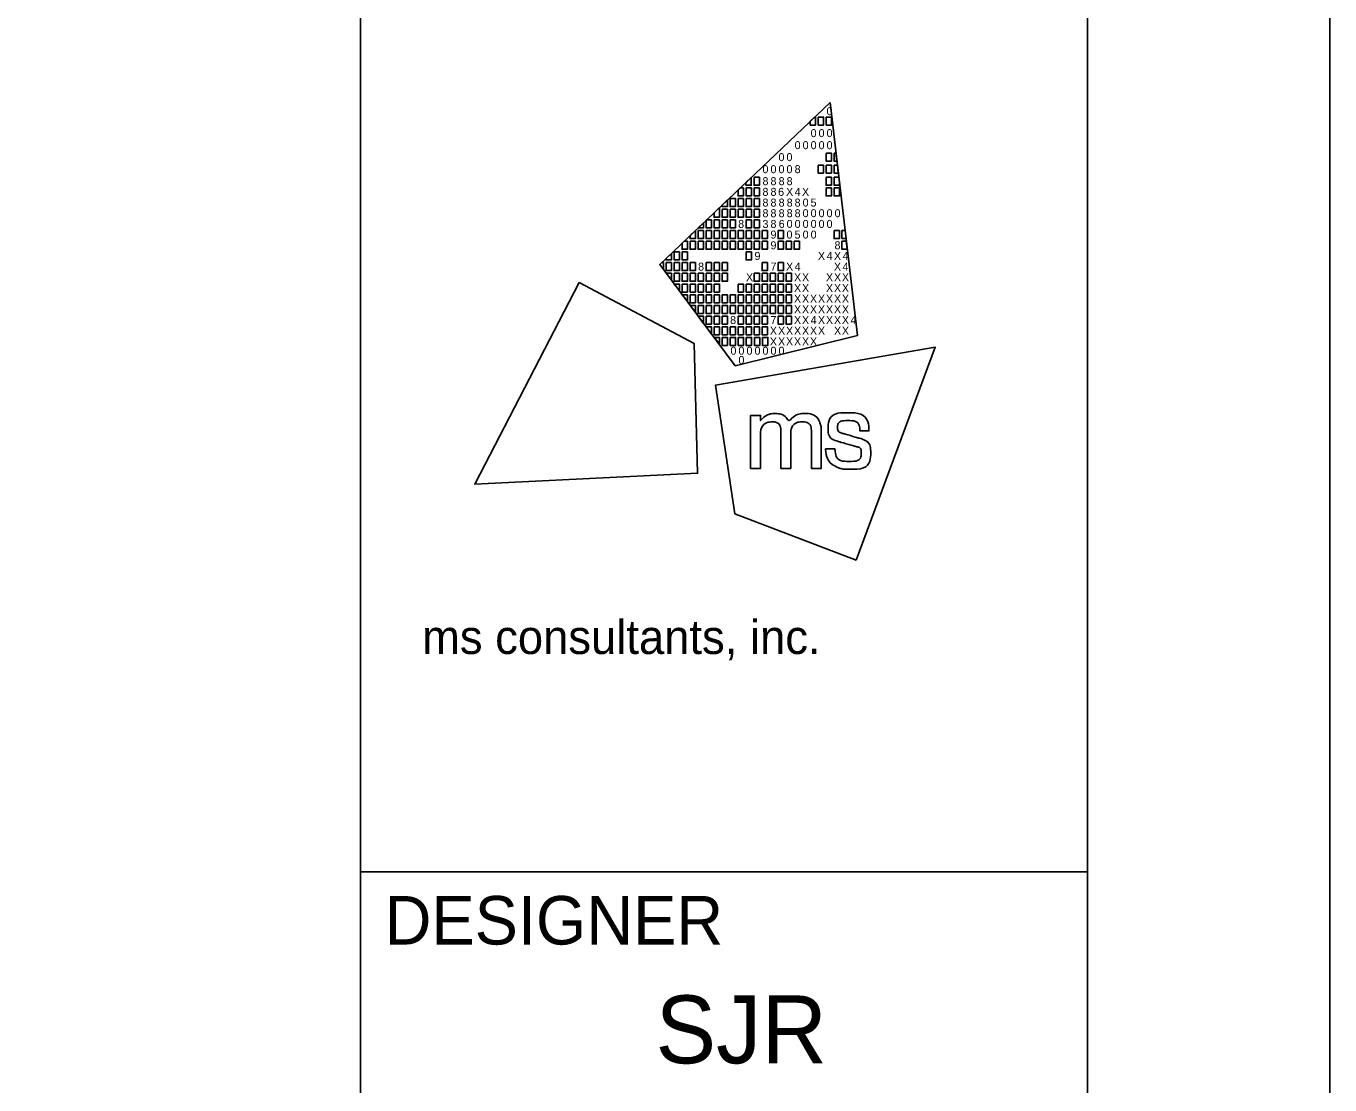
# Model space of a CAD drawing. Extents: x 0 to 34, y 0 to 22.
# Drawn here: x 31.31 to 34, y 2.061 to 4.243 of the extents above; entities that cross this region are included whole.
import ezdxf

# ---------------------------------------------------------------- set-up
doc = ezdxf.new("R2010")
doc.units = 0
for name, color, linetype in [('SH_Border', 7, 'Continuous'), ('SH_Cut_Line', 7, 'Continuous'), ('SH_Data', 7, 'Continuous'), ('SH_Text', 7, 'Continuous')]:
    doc.layers.add(name, color=color, linetype=linetype)

msp = doc.modelspace()

# ---------------------------------------------------------------- linework, layer by layer
at = {"layer": 'SH_Border'}
for p, q in [((32, 0.5), (32, 21.5)), ((32, 2.5), (33.5, 2.5))]:
    msp.add_line(p, q, dxfattribs=at)
msp.add_lwpolyline([(1.5, 21.5), (33.5, 21.5), (33.5, 0.5), (1.5, 0.5)], close=True, dxfattribs=at)
at = {"layer": 'SH_Cut_Line'}
msp.add_lwpolyline([(0, 0), (34, 0), (34, 22), (0, 22)], close=True, dxfattribs=at)
at = {"layer": 'SH_Data'}
msp.add_line((32.75, 3.5), (32.75, 3.5), dxfattribs=at)
at = {"layer": 'SH_Text'}
for p, q in [((32.6175, 3.7519), (32.9688, 4.0861)), ((32.9688, 4.0861), (32.9688, 4.0861)), ((32.9688, 4.0861), (33.0253, 3.6052)), ((32.773, 3.543), (32.6175, 3.7519)), ((33.0253, 3.6052), (32.773, 3.543))]:
    msp.add_line(p, q, dxfattribs=at)
for points in [[(32.9279, 4.0472), (32.9369, 4.0558), (32.9389, 4.0558), (32.9389, 4.0393), (32.9279, 4.0393)], [(32.9444, 4.0558), (32.9554, 4.0558), (32.9554, 4.0393), (32.9444, 4.0393)], [(32.9609, 4.0558), (32.9719, 4.0558), (32.9719, 4.0393), (32.9609, 4.0393)], [(32.9606, 3.9815), (32.9716, 3.9815), (32.9716, 3.965), (32.9606, 3.965)], [(32.9771, 3.9815), (32.9811, 3.9815), (32.983, 3.965), (32.9771, 3.965)], [(32.9441, 3.9567), (32.9551, 3.9567), (32.9551, 3.9402), (32.9441, 3.9402)], [(32.9606, 3.9567), (32.9716, 3.9567), (32.9716, 3.9402), (32.9606, 3.9402)], [(32.9771, 3.9567), (32.984, 3.9567), (32.9859, 3.9402), (32.9771, 3.9402)], [(32.7953, 3.9211), (32.8064, 3.9316), (32.8064, 3.9154), (32.7953, 3.9154)], [(32.8123, 3.9319), (32.8233, 3.9319), (32.8233, 3.9154), (32.8123, 3.9154)], [(32.9606, 3.9319), (32.9716, 3.9319), (32.9716, 3.9154), (32.9606, 3.9154)], [(32.9771, 3.9319), (32.9869, 3.9319), (32.9881, 3.9218), (32.9881, 3.9154), (32.9771, 3.9154)], [(32.7958, 3.9099), (32.8068, 3.9099), (32.8068, 3.8934), (32.7958, 3.8934)], [(32.8123, 3.9099), (32.8233, 3.9099), (32.8233, 3.8934), (32.8123, 3.8934)], [(32.9606, 3.9099), (32.9716, 3.9099), (32.9716, 3.8934), (32.9606, 3.8934)], [(32.9771, 3.9099), (32.9881, 3.9099), (32.9881, 3.8934), (32.9771, 3.8934)], [(32.7627, 3.8879), (32.7737, 3.8879), (32.7737, 3.8714), (32.7627, 3.8714)], [(32.7793, 3.8879), (32.7903, 3.8879), (32.7903, 3.8714), (32.7793, 3.8714)], [(32.7958, 3.8879), (32.8068, 3.8879), (32.8068, 3.8714), (32.7958, 3.8714)], [(32.8123, 3.8879), (32.8233, 3.8879), (32.8233, 3.8714), (32.8123, 3.8714)], [(32.7462, 3.8659), (32.7572, 3.8659), (32.7572, 3.8494), (32.7462, 3.8494)], [(32.7627, 3.8659), (32.7737, 3.8659), (32.7737, 3.8494), (32.7627, 3.8494)], [(32.7793, 3.8659), (32.7903, 3.8659), (32.7903, 3.8494), (32.7793, 3.8494)], [(32.7958, 3.8659), (32.8068, 3.8659), (32.8068, 3.8494), (32.7958, 3.8494)], [(32.8123, 3.8659), (32.8233, 3.8659), (32.8233, 3.8494), (32.8123, 3.8494)], [(32.6967, 3.8218), (32.7077, 3.8218), (32.7077, 3.8053), (32.6967, 3.8053)], [(32.7132, 3.8218), (32.7242, 3.8218), (32.7242, 3.8053), (32.7132, 3.8053)], [(32.7297, 3.8439), (32.7407, 3.8439), (32.7407, 3.8273), (32.7297, 3.8273)], [(32.7297, 3.8218), (32.7407, 3.8218), (32.7407, 3.8053), (32.7297, 3.8053)], [(32.7462, 3.8439), (32.7572, 3.8439), (32.7572, 3.8273), (32.7462, 3.8273)], [(32.7462, 3.8218), (32.7572, 3.8218), (32.7572, 3.8053), (32.7462, 3.8053)], [(32.7627, 3.8439), (32.7737, 3.8439), (32.7737, 3.8273), (32.7627, 3.8273)], [(32.7627, 3.8218), (32.7737, 3.8218), (32.7737, 3.8053), (32.7627, 3.8053)], [(32.7793, 3.8218), (32.7903, 3.8218), (32.7903, 3.8053), (32.7793, 3.8053)], [(32.7958, 3.8439), (32.8068, 3.8439), (32.8068, 3.8273), (32.7958, 3.8273)], [(32.7958, 3.8218), (32.8068, 3.8218), (32.8068, 3.8053), (32.7958, 3.8053)], [(32.8123, 3.8439), (32.8233, 3.8439), (32.8233, 3.8273), (32.8123, 3.8273)], [(32.8123, 3.8218), (32.8233, 3.8218), (32.8233, 3.8053), (32.8123, 3.8053)], [(32.8288, 3.8218), (32.8398, 3.8218), (32.8398, 3.8053), (32.8288, 3.8053)], [(32.8618, 3.8218), (32.8728, 3.8218), (32.8728, 3.8053), (32.8618, 3.8053)], [(32.9771, 3.8218), (32.9881, 3.8218), (32.9881, 3.8053), (32.9771, 3.8053)], [(32.9935, 3.8218), (32.9998, 3.8218), (33.0018, 3.8053), (32.9935, 3.8053)], [(32.6802, 3.7998), (32.6912, 3.7998), (32.6912, 3.7833), (32.6802, 3.7833)], [(32.6967, 3.7998), (32.7077, 3.7998), (32.7077, 3.7833), (32.6967, 3.7833)], [(32.7132, 3.7998), (32.7242, 3.7998), (32.7242, 3.7833), (32.7132, 3.7833)], [(32.7297, 3.7998), (32.7407, 3.7998), (32.7407, 3.7833), (32.7297, 3.7833)], [(32.7462, 3.7998), (32.7572, 3.7998), (32.7572, 3.7833), (32.7462, 3.7833)], [(32.7627, 3.7998), (32.7737, 3.7998), (32.7737, 3.7833), (32.7627, 3.7833)], [(32.7793, 3.7998), (32.7903, 3.7998), (32.7903, 3.7833), (32.7793, 3.7833)], [(32.7958, 3.7998), (32.8068, 3.7998), (32.8068, 3.7833), (32.7958, 3.7833)], [(32.8123, 3.7998), (32.8233, 3.7998), (32.8233, 3.7833), (32.8123, 3.7833)], [(32.8288, 3.7998), (32.8398, 3.7998), (32.8398, 3.7833), (32.8288, 3.7833)], [(32.8618, 3.7998), (32.8728, 3.7998), (32.8728, 3.7833), (32.8618, 3.7833)], [(32.8783, 3.7998), (32.8893, 3.7998), (32.8893, 3.7833), (32.8783, 3.7833)], [(32.8947, 3.7998), (32.9057, 3.7998), (32.9057, 3.7833), (32.8947, 3.7833)], [(32.9935, 3.7998), (33.0024, 3.7998), (33.0044, 3.7833), (32.9935, 3.7833)], [(32.6471, 3.7778), (32.6581, 3.7778), (32.6581, 3.7613), (32.6471, 3.7613)], [(32.6637, 3.7778), (32.6747, 3.7778), (32.6747, 3.7613), (32.6637, 3.7613)], [(32.7958, 3.7778), (32.8068, 3.7778), (32.8068, 3.7613), (32.7958, 3.7613)], [(32.6306, 3.7558), (32.6416, 3.7558), (32.6416, 3.7393), (32.6306, 3.7393)], [(32.6471, 3.7558), (32.6581, 3.7558), (32.6581, 3.7393), (32.6471, 3.7393)], [(32.6637, 3.7558), (32.6747, 3.7558), (32.6747, 3.7393), (32.6637, 3.7393)], [(32.6802, 3.7558), (32.6912, 3.7558), (32.6912, 3.7393), (32.6802, 3.7393)], [(32.7132, 3.7558), (32.7242, 3.7558), (32.7242, 3.7393), (32.7132, 3.7393)], [(32.7297, 3.7558), (32.7407, 3.7558), (32.7407, 3.7393), (32.7297, 3.7393)], [(32.7462, 3.7558), (32.7572, 3.7558), (32.7572, 3.7393), (32.7462, 3.7393)], [(32.8288, 3.7558), (32.8398, 3.7558), (32.8398, 3.7393), (32.8288, 3.7393)], [(32.8618, 3.7558), (32.8728, 3.7558), (32.8728, 3.7393), (32.8618, 3.7393)], [(32.6306, 3.7338), (32.6416, 3.7338), (32.6416, 3.72)], [(32.6471, 3.7338), (32.6581, 3.7338), (32.6581, 3.7173), (32.6471, 3.7173)], [(32.6471, 3.7117), (32.6581, 3.7117), (32.6581, 3.698)], [(32.6637, 3.7338), (32.6747, 3.7338), (32.6747, 3.7173), (32.6637, 3.7173)], [(32.6637, 3.7117), (32.6747, 3.7117), (32.6747, 3.6952), (32.6637, 3.6952)], [(32.6802, 3.7338), (32.6912, 3.7338), (32.6912, 3.7173), (32.6802, 3.7173)], [(32.6802, 3.7117), (32.6912, 3.7117), (32.6912, 3.6952), (32.6802, 3.6952)], [(32.6967, 3.7338), (32.7077, 3.7338), (32.7077, 3.7173), (32.6967, 3.7173)], [(32.6967, 3.7117), (32.7077, 3.7117), (32.7077, 3.6952), (32.6967, 3.6952)], [(32.7132, 3.7338), (32.7242, 3.7338), (32.7242, 3.7173), (32.7132, 3.7173)], [(32.7132, 3.7117), (32.7242, 3.7117), (32.7242, 3.6952), (32.7132, 3.6952)], [(32.7297, 3.7338), (32.7407, 3.7338), (32.7407, 3.7173), (32.7297, 3.7173)], [(32.7297, 3.7117), (32.7407, 3.7117), (32.7407, 3.6952), (32.7297, 3.6952)], [(32.7462, 3.7338), (32.7572, 3.7338), (32.7572, 3.7173), (32.7462, 3.7173)], [(32.7793, 3.7117), (32.7903, 3.7117), (32.7903, 3.6952), (32.7793, 3.6952)], [(32.7958, 3.7117), (32.8068, 3.7117), (32.8068, 3.6952), (32.7958, 3.6952)], [(32.8123, 3.7338), (32.8233, 3.7338), (32.8233, 3.7173), (32.8123, 3.7173)], [(32.8123, 3.7117), (32.8233, 3.7117), (32.8233, 3.6952), (32.8123, 3.6952)], [(32.8288, 3.7338), (32.8398, 3.7338), (32.8398, 3.7173), (32.8288, 3.7173)], [(32.8288, 3.7117), (32.8398, 3.7117), (32.8398, 3.6952), (32.8288, 3.6952)], [(32.8453, 3.7338), (32.8563, 3.7338), (32.8563, 3.7173), (32.8453, 3.7173)], [(32.8453, 3.7117), (32.8563, 3.7117), (32.8563, 3.6952), (32.8453, 3.6952)], [(32.8618, 3.7338), (32.8728, 3.7338), (32.8728, 3.7173), (32.8618, 3.7173)], [(32.8618, 3.7117), (32.8728, 3.7117), (32.8728, 3.6952), (32.8618, 3.6952)], [(32.8783, 3.7338), (32.8893, 3.7338), (32.8893, 3.7173), (32.8783, 3.7173)], [(32.8783, 3.7117), (32.8893, 3.7117), (32.8893, 3.6952), (32.8783, 3.6952)], [(32.6637, 3.6897), (32.6747, 3.6897), (32.6747, 3.676)], [(32.6747, 3.6897), (32.6747, 3.6897), (32.6747, 3.6897)], [(32.6802, 3.6897), (32.6912, 3.6897), (32.6912, 3.6732), (32.6802, 3.6732)], [(32.6967, 3.6897), (32.7077, 3.6897), (32.7077, 3.6732), (32.6967, 3.6732)], [(32.7132, 3.6897), (32.7242, 3.6897), (32.7242, 3.6732), (32.7132, 3.6732)], [(32.7297, 3.6897), (32.7407, 3.6897), (32.7407, 3.6732), (32.7297, 3.6732)], [(32.7462, 3.6897), (32.7572, 3.6897), (32.7572, 3.6732), (32.7462, 3.6732)], [(32.7627, 3.6897), (32.7737, 3.6897), (32.7737, 3.6732), (32.7627, 3.6732)], [(32.7793, 3.6897), (32.7903, 3.6897), (32.7903, 3.6732), (32.7793, 3.6732)], [(32.7958, 3.6897), (32.8068, 3.6897), (32.8068, 3.6732), (32.7958, 3.6732)], [(32.8123, 3.6897), (32.8233, 3.6897), (32.8233, 3.6732), (32.8123, 3.6732)], [(32.8288, 3.6897), (32.8398, 3.6897), (32.8398, 3.6732), (32.8288, 3.6732)], [(32.8453, 3.6897), (32.8563, 3.6897), (32.8563, 3.6732), (32.8453, 3.6732)], [(32.8618, 3.6897), (32.8728, 3.6897), (32.8728, 3.6732), (32.8618, 3.6732)], [(32.8783, 3.6897), (32.8893, 3.6897), (32.8893, 3.6732), (32.8783, 3.6732)], [(32.6802, 3.6677), (32.6912, 3.6677), (32.6912, 3.654)], [(32.6967, 3.6677), (32.7077, 3.6677), (32.7077, 3.6512), (32.6967, 3.6512)], [(32.7132, 3.6677), (32.7242, 3.6677), (32.7242, 3.6512), (32.7132, 3.6512)], [(32.7297, 3.6677), (32.7407, 3.6677), (32.7407, 3.6512), (32.7297, 3.6512)], [(32.7462, 3.6677), (32.7572, 3.6677), (32.7572, 3.6512), (32.7462, 3.6512)], [(32.7627, 3.6677), (32.7737, 3.6677), (32.7737, 3.6512), (32.7627, 3.6512)], [(32.7793, 3.6677), (32.7903, 3.6677), (32.7903, 3.6512), (32.7793, 3.6512)], [(32.7958, 3.6677), (32.8068, 3.6677), (32.8068, 3.6512), (32.7958, 3.6512)], [(32.8123, 3.6677), (32.8233, 3.6677), (32.8233, 3.6512), (32.8123, 3.6512)], [(32.8288, 3.6677), (32.8398, 3.6677), (32.8398, 3.6512), (32.8288, 3.6512)], [(32.8453, 3.6677), (32.8563, 3.6677), (32.8563, 3.6512), (32.8453, 3.6512)], [(32.8618, 3.6677), (32.8728, 3.6677), (32.8728, 3.6512), (32.8618, 3.6512)], [(32.8783, 3.6677), (32.8893, 3.6677), (32.8893, 3.6512), (32.8783, 3.6512)], [(32.7077, 3.6305), (32.6965, 3.6457), (32.7077, 3.6457)], [(32.7132, 3.6457), (32.7242, 3.6457), (32.7242, 3.6292), (32.7132, 3.6292)], [(32.7297, 3.6457), (32.7407, 3.6457), (32.7407, 3.6292), (32.7297, 3.6292)], [(32.7462, 3.6457), (32.7572, 3.6457), (32.7572, 3.6292), (32.7462, 3.6292)], [(32.7793, 3.6457), (32.7903, 3.6457), (32.7903, 3.6292), (32.7793, 3.6292)], [(32.7958, 3.6457), (32.8068, 3.6457), (32.8068, 3.6292), (32.7958, 3.6292)], [(32.8123, 3.6457), (32.8233, 3.6457), (32.8233, 3.6292), (32.8123, 3.6292)], [(32.8288, 3.6457), (32.8398, 3.6457), (32.8398, 3.6292), (32.8288, 3.6292)], [(32.8618, 3.6457), (32.8728, 3.6457), (32.8728, 3.6292), (32.8618, 3.6292)], [(32.8783, 3.6457), (32.8893, 3.6457), (32.8893, 3.6292), (32.8783, 3.6292)], [(32.724, 3.6082), (32.7132, 3.6237), (32.7242, 3.6237)], [(32.7297, 3.6237), (32.7407, 3.6237), (32.7407, 3.6072), (32.7297, 3.6072)], [(32.7462, 3.6237), (32.7572, 3.6237), (32.7572, 3.6072), (32.7462, 3.6072)], [(32.7627, 3.6237), (32.7737, 3.6237), (32.7737, 3.6072), (32.7627, 3.6072)], [(32.7793, 3.6237), (32.7903, 3.6237), (32.7903, 3.6072), (32.7793, 3.6072)], [(32.7958, 3.6237), (32.8068, 3.6237), (32.8068, 3.6072), (32.7958, 3.6072)], [(32.8123, 3.6237), (32.8233, 3.6237), (32.8233, 3.6072), (32.8123, 3.6072)], [(32.8288, 3.6237), (32.8398, 3.6237), (32.8398, 3.6072), (32.8288, 3.6072)], [(32.7302, 3.6017), (32.7407, 3.6017), (32.7408, 3.5875)], [(32.7463, 3.6017), (32.7573, 3.6017), (32.7573, 3.5852), (32.7463, 3.5852)], [(32.763, 3.6017), (32.774, 3.6017), (32.774, 3.5852), (32.763, 3.5852)], [(32.7794, 3.6017), (32.7904, 3.6017), (32.7904, 3.5852), (32.7794, 3.5852)], [(32.796, 3.6017), (32.807, 3.6017), (32.807, 3.5852), (32.796, 3.5852)], [(32.8129, 3.6017), (32.8239, 3.6017), (32.8239, 3.5851), (32.8129, 3.5851)], [(32.8296, 3.6017), (32.8406, 3.6017), (32.8406, 3.5851), (32.8296, 3.5851)]]:
    msp.add_lwpolyline(points, close=True, dxfattribs=at)
for points in [[(32.7903, 3.9099), (32.7836, 3.9099), (32.7793, 3.9058), (32.7793, 3.8934), (32.7903, 3.8934), (32.7903, 3.9099)], [(32.7572, 3.8849), (32.7462, 3.8744), (32.7462, 3.8714), (32.7572, 3.8714), (32.7572, 3.8849)], [(32.7407, 3.8691), (32.7297, 3.8587), (32.7297, 3.8494), (32.7407, 3.8494), (32.7407, 3.8691)], [(32.6912, 3.822), (32.6802, 3.8115), (32.6802, 3.8053), (32.6912, 3.8053), (32.6912, 3.822)], [(32.7077, 3.8377), (32.6968, 3.8273), (32.7077, 3.8273), (32.7077, 3.8377)], [(32.7242, 3.8439), (32.7141, 3.8439), (32.7132, 3.843), (32.7132, 3.8273), (32.7242, 3.8273), (32.7242, 3.8439)], [(32.6747, 3.7998), (32.6679, 3.7998), (32.6637, 3.7958), (32.6637, 3.7833), (32.6747, 3.7833), (32.6747, 3.7998)], [(32.6416, 3.7749), (32.6306, 3.7644), (32.6306, 3.7613), (32.6416, 3.7613), (32.6416, 3.7749)], [(32.6251, 3.7558), (32.6216, 3.7558), (32.6175, 3.7519), (32.6251, 3.7417), (32.6251, 3.7558)], [(32.4512, 3.7149), (32.2359, 3.2988), (32.6956, 3.3215), (32.6884, 3.5892), (32.4512, 3.7149)], [(33.0229, 3.1422), (33.1859, 3.5814), (32.7324, 3.5029), (32.7722, 3.2381), (33.0229, 3.1422)]]:
    msp.add_lwpolyline(points, dxfattribs=at)
for points in [[(32.8048, 3.3315), (32.8048, 3.3315), (32.8048, 3.4409), (32.8048, 3.4409), (32.8048, 3.4409), (32.8255, 3.4409), (32.8255, 3.4409), (32.8255, 3.4409), (32.8255, 3.4297), (32.8255, 3.4297), (32.8346, 3.4399), (32.8457, 3.4445), (32.8555, 3.4445), (32.8688, 3.4445), (32.8791, 3.4372), (32.8837, 3.4266), (32.8915, 3.4381), (32.905, 3.4446), (32.9166, 3.4446), (32.9325, 3.4446), (32.9451, 3.435), (32.9494, 3.4213), (32.9494, 3.4212), (32.9494, 3.4212), (32.9494, 3.4212), (32.9501, 3.419), (32.9506, 3.4172), (32.9506, 3.4071), (32.9506, 3.4071), (32.9506, 3.3314), (32.9506, 3.3314), (32.9506, 3.3314), (32.9303, 3.3314), (32.9303, 3.3314), (32.9303, 3.3314), (32.9303, 3.4048), (32.9303, 3.4048), (32.9303, 3.4201), (32.9219, 3.4274), (32.911, 3.4274), (32.8995, 3.4274), (32.8879, 3.4171), (32.8879, 3.4001), (32.8879, 3.4001), (32.8879, 3.3315), (32.8879, 3.3315), (32.8879, 3.3315), (32.8674, 3.3315), (32.8674, 3.3315), (32.8674, 3.3315), (32.8674, 3.4059), (32.8674, 3.4059), (32.8674, 3.4203), (32.8588, 3.4274), (32.8496, 3.4274), (32.8384, 3.4274), (32.8254, 3.417), (32.8254, 3.3962), (32.8254, 3.3962), (32.8254, 3.3315), (32.8254, 3.3315), (32.8254, 3.3315), (32.8048, 3.3315), (32.8048, 3.3315)], [(32.9595, 3.3709), (32.9595, 3.3709), (32.9595, 3.3717), (32.9595, 3.3717), (32.9595, 3.3717), (32.9603, 3.3717), (32.9603, 3.3717), (32.9603, 3.3717), (32.9783, 3.3717), (32.9783, 3.3717), (32.9783, 3.3717), (32.9789, 3.3717), (32.9789, 3.3717), (32.9789, 3.3717), (32.979, 3.371), (32.979, 3.371), (32.9803, 3.3554), (32.9887, 3.346), (33.009, 3.346), (33.0273, 3.346), (33.0333, 3.3554), (33.0333, 3.3631), (33.0333, 3.3732), (33.0256, 3.3758), (33.0175, 3.378), (33.0175, 3.378), (32.987, 3.3867), (32.987, 3.3867), (32.972, 3.3909), (32.9648, 3.4019), (32.9648, 3.4142), (32.9648, 3.4303), (32.9768, 3.4462), (33.0052, 3.4462), (33.0348, 3.4462), (33.0489, 3.4285), (33.0489, 3.4095), (33.0489, 3.4095), (33.0489, 3.4087), (33.0489, 3.4087), (33.0489, 3.4087), (33.0482, 3.4087), (33.0482, 3.4087), (33.0482, 3.4087), (33.0312, 3.4087), (33.0312, 3.4087), (33.0312, 3.4087), (33.0305, 3.4087), (33.0305, 3.4087), (33.0305, 3.4087), (33.0305, 3.4094), (33.0305, 3.4094), (33.0301, 3.4208), (33.0226, 3.43), (33.0056, 3.43), (32.9891, 3.43), (32.9843, 3.4218), (32.9843, 3.4157), (32.9843, 3.4108), (32.9869, 3.4059), (32.9959, 3.4033), (32.9959, 3.4033), (33.0255, 3.3948), (33.0255, 3.3948), (33.0462, 3.3889), (33.0527, 3.3777), (33.0527, 3.3639), (33.0527, 3.3462), (33.041, 3.3298), (33.0087, 3.3298), (32.9952, 3.3298), (32.9877, 3.3321), (32.9823, 3.3348), (32.969, 3.3414), (32.9609, 3.3536), (32.9595, 3.3709)]]:
    msp.add_open_spline(points, degree=3, dxfattribs=at)

# ---------------------------------------------------------------- texts
at = {"layer": 'SH_Border'}
msp.add_text('ms consultants, inc.', height=0.07, rotation=360, dxfattribs=at).set_placement((32.1273, 2.9489))
at = {"layer": 'SH_Data'}
for s, height, p in [('DESIGNER', 0.1, (32.05, 2.35)), ('SJR', 0.14, (32.6089, 2.105))]:
    msp.add_text(s, height=height, dxfattribs=at).set_placement(p)
at = {"layer": 'SH_Text'}
for s, p in [('0', (32.9617, 4.0597)), ('0', (32.9288, 4.0145)), ('0', (32.9452, 4.0145)), ('0', (32.9617, 4.0145)), ('0', (32.8625, 3.965)), ('0', (32.879, 3.965)), ('0', (32.8958, 3.9897)), ('0', (32.9123, 3.9897)), ('0', (32.9288, 3.9897)), ('0', (32.9452, 3.9897)), ('0', (32.9617, 3.9897)), ('0', (32.8295, 3.9402)), ('0', (32.846, 3.9402)), ('0', (32.8625, 3.9402)), ('0', (32.879, 3.9402)), ('8', (32.8958, 3.9402)), ('8', (32.8295, 3.9154)), ('8', (32.846, 3.9154)), ('8', (32.8628, 3.9154)), ('8', (32.8793, 3.9154)), ('8', (32.8295, 3.8934)), ('8', (32.846, 3.8934)), ('6', (32.8618, 3.8934)), ('X', (32.8781, 3.8934)), ('4', (32.8958, 3.8934)), ('X', (32.911, 3.8934)), ('8', (32.8295, 3.8713)), ('8', (32.846, 3.8713)), ('8', (32.8628, 3.8713)), ('8', (32.8794, 3.8713)), ('8', (32.8958, 3.8713)), ('0', (32.9123, 3.8713)), ('5', (32.9287, 3.8713)), ('8', (32.8295, 3.8494)), ('8', (32.846, 3.8494)), ('8', (32.8628, 3.8494)), ('8', (32.8794, 3.8494)), ('8', (32.8958, 3.8494)), ('0', (32.9123, 3.8494)), ('0', (32.9288, 3.8494)), ('0', (32.9452, 3.8494)), ('0', (32.9617, 3.8494)), ('0', (32.9782, 3.8494)), ('8', (32.7793, 3.8273)), ('3', (32.8295, 3.8273)), ('8', (32.846, 3.8273)), ('9', (32.846, 3.8053)), ('6', (32.8629, 3.8273)), ('0', (32.879, 3.8053)), ('0', (32.8793, 3.8273)), ('5', (32.8957, 3.8053)), ('0', (32.8958, 3.8273)), ('0', (32.9123, 3.8273)), ('0', (32.9123, 3.8053)), ('0', (32.9288, 3.8273)), ('0', (32.9288, 3.8053)), ('0', (32.9452, 3.8273)), ('0', (32.9617, 3.8273)), ('9', (32.846, 3.7833)), ('8', (32.9781, 3.7833)), ('9', (32.813, 3.7613)), ('X', (32.9439, 3.7613)), ('4', (32.9617, 3.7613)), ('X', (32.9769, 3.7613)), ('4', (32.9946, 3.7613)), ('8', (32.6967, 3.7393)), ('7', (32.846, 3.7393)), ('X', (32.8781, 3.7393)), ('4', (32.8958, 3.7393)), ('X', (32.9769, 3.7393)), ('4', (32.9946, 3.7393)), ('X', (32.7955, 3.7173)), ('X', (32.8945, 3.7173)), ('X', (32.8945, 3.6952)), ('X', (32.911, 3.7173)), ('X', (32.911, 3.6952)), ('X', (32.9604, 3.7173)), ('X', (32.9604, 3.6952)), ('X', (32.9769, 3.7173)), ('X', (32.9769, 3.6952)), ('X', (32.9933, 3.7173)), ('X', (32.9933, 3.6952)), ('X', (32.8945, 3.6732)), ('X', (32.911, 3.6732)), ('X', (32.9274, 3.6732)), ('X', (32.9439, 3.6732)), ('X', (32.9604, 3.6732)), ('X', (32.9769, 3.6732)), ('X', (32.9933, 3.6732)), ('X', (32.8945, 3.6512)), ('X', (32.911, 3.6512)), ('X', (32.9274, 3.6512)), ('X', (32.9439, 3.6512)), ('X', (32.9604, 3.6512)), ('X', (32.9769, 3.6512)), ('X', (32.9933, 3.6512)), ('8', (32.7627, 3.6292)), ('7', (32.846, 3.6292)), ('X', (32.8945, 3.6292)), ('X', (32.911, 3.6292)), ('4', (32.9288, 3.6292)), ('X', (32.9439, 3.6292)), ('X', (32.9604, 3.6292)), ('X', (32.9769, 3.6292)), ('X', (32.9933, 3.6292)), ('4', (33.0111, 3.6292)), ('X', (32.8447, 3.6072)), ('X', (32.8616, 3.6072)), ('X', (32.878, 3.6072)), ('X', (32.8945, 3.6072)), ('X', (32.911, 3.6072)), ('X', (32.9274, 3.6072)), ('X', (32.9439, 3.6072)), ('X', (32.9771, 3.6072)), ('X', (32.9933, 3.6072)), ('0', (32.7634, 3.5659)), ('0', (32.7799, 3.5659)), ('0', (32.7965, 3.5659)), ('0', (32.813, 3.5659)), ('0', (32.8295, 3.5659)), ('X', (32.8447, 3.5851)), ('0', (32.846, 3.5659)), ('X', (32.8616, 3.5851)), ('0', (32.8625, 3.5659)), ('X', (32.878, 3.5851)), ('X', (32.8945, 3.5851)), ('X', (32.911, 3.5851)), ('X', (32.9274, 3.5851)), ('0', (32.7799, 3.5467))]:
    msp.add_text(s, height=0.0165, rotation=360, dxfattribs=at).set_placement(p)

doc.saveas('drawing.dxf')
